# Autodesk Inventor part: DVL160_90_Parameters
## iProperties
Created: 2009-09
Part Number: DVL160_90_Parameters
Document SubType Name: Modeling
Designer: TB
Density: 1 g/cm^3
Slaglengde: 100.000 mm
Vinkel_Plussport: 0.00 deg
Vinkel_Minusport: 0.00 deg
Forlengelse_rør: 0.000 mm
Author: TB
